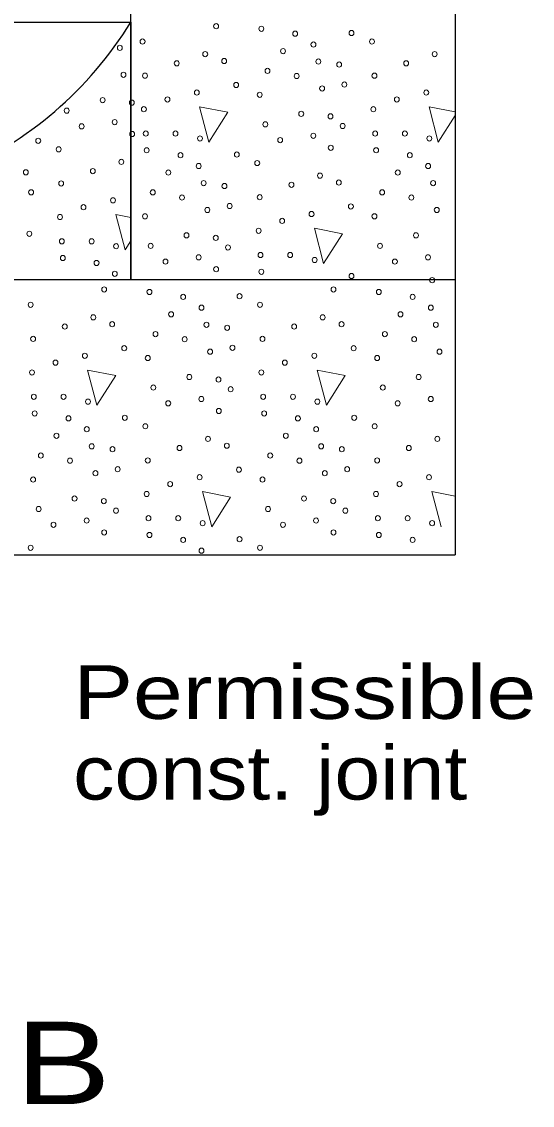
# Model space of a CAD drawing. Extents: x -410.5 to -376.5, y 1617.6 to 1661.6.
# Drawn here: x -391.413 to -389.927, y 1650.531 to 1653.682 of the extents above; entities that cross this region are included whole.
import ezdxf

# ---------------------------------------------------------------- set-up
doc = ezdxf.new("R2010")
doc.units = 0
doc.header["$LTSCALE"] = 0.062
doc.layers.add('1', color=7, linetype='Continuous', lineweight=13)

msp = doc.modelspace()

# ---------------------------------------------------------------- linework, layer by layer
at = {"layer": '1', "lineweight": 25}
for p, q in [((-393.83325, 1653.681), (-391.09567, 1653.681)), ((-390.15167, 1652.9315), (-391.09567, 1652.9315))]:
    msp.add_line(p, q, dxfattribs=at)
at = {"layer": '1'}
for p, q in [((-390.15158, 1653.41992), (-390.22783, 1653.43475)), ((-390.22783, 1653.43475), (-390.20083, 1653.33233)), ((-390.20083, 1653.33233), (-390.15158, 1653.40975)), ((-391.09567, 1653.11275), (-391.1395, 1653.12133)), ((-391.1395, 1653.12133), (-391.1125, 1653.01892)), ((-391.1125, 1653.01892), (-391.09567, 1653.04542)), ((-390.21983, 1652.31592), (-390.19292, 1652.21358)), ((-390.15175, 1652.30267), (-390.21983, 1652.31592))]:
    msp.add_line(p, q, dxfattribs=at)
at = {"layer": '1', "lineweight": 25}
for points in [[(-391.09567, 1656.03808), (-391.07275, 1656.04358), (-390.86258, 1655.99133), (-390.75258, 1656.01533), (-390.70333, 1656.02033), (-390.53658, 1656.01175), (-390.38608, 1655.98), (-390.15167, 1656.00792), (-390.15167, 1652.13192)], [(-391.09567, 1652.9315), (-391.09567, 1653.681), (-391.09567, 1656.03808)], [(-391.09567, 1653.681), (-391.09567, 1652.9315), (-393.18867, 1652.9315)], [(-390.15167, 1652.9315), (-394.16367, 1652.9315), (-394.16367, 1652.78158), (-393.83325, 1652.78158), (-393.83325, 1652.63167), (-394.27908, 1652.63167), (-394.54583, 1652.78158), (-394.77725, 1652.78158)], [(-394.77725, 1652.78158), (-394.77725, 1652.13192), (-390.15167, 1652.13192)]]:
    msp.add_lwpolyline(points, dxfattribs=at)
at = {"layer": '1'}
for points in [[(-390.89542, 1653.43475), (-390.86842, 1653.33233), (-390.81342, 1653.41875)], [(-390.56158, 1653.08142), (-390.53458, 1652.97892), (-390.47967, 1653.06542)], [(-391.22117, 1652.66925), (-391.19417, 1652.56683), (-391.13917, 1652.65333)], [(-390.55358, 1652.66925), (-390.52667, 1652.56683), (-390.47167, 1652.65333)], [(-390.88733, 1652.31592), (-390.86033, 1652.21358), (-390.8055, 1652.3)]]:
    msp.add_lwpolyline(points, close=True, dxfattribs=at)
at = {"layer": '1', "lineweight": 25}
msp.add_ellipse((-391.98484, 1654.29513), major_axis=(0, 1.12397), ratio=0.944543, start_param=3.5092821, end_param=4.1343748, dxfattribs=at)
at = {"layer": '1'}
for centre, major_axis in [((-390.8475, 1653.66907), (0, -0.00756)), ((-390.71567, 1653.66177), (0, -0.00756)), ((-390.4534, 1653.64934), (0, -0.00756)), ((-391.06144, 1653.62455), (0, -0.00756)), ((-390.61738, 1653.64746), (0, 0.00756)), ((-390.39393, 1653.62455), (0, -0.00756)), ((-391.12767, 1653.60631), (0, 0.00756)), ((-390.87904, 1653.58798), (0, -0.00756)), ((-390.65259, 1653.59687), (0, 0.00756)), ((-390.56426, 1653.61595), (0, 0.00756)), ((-390.21154, 1653.58798), (0, -0.00756)), ((-390.96198, 1653.5613), (0, -0.00756)), ((-390.82409, 1653.56796), (0, -0.00756)), ((-390.5498, 1653.56637), (0, 0.00756)), ((-390.48944, 1653.55771), (0, -0.00756)), ((-390.29447, 1653.5613), (0, -0.00756)), ((-391.11693, 1653.52804), (0, 0.00756)), ((-391.05421, 1653.52526), (0, -0.00756)), ((-390.69793, 1653.53933), (0, 0.00756)), ((-390.61293, 1653.52438), (0, 0.00756)), ((-390.3867, 1653.52526), (0, -0.00756)), ((-390.78899, 1653.49829), (0, 0.00756)), ((-390.47414, 1653.49958), (0, -0.00756)), ((-390.90341, 1653.47632), (0, -0.00756)), ((-390.72046, 1653.46967), (0, 0.00756)), ((-390.53906, 1653.4881), (0, 0.00756)), ((-390.2359, 1653.47632), (0, -0.00756)), ((-391.17756, 1653.45431), (0, 0.00756)), ((-391.09251, 1653.44695), (0, 0.00756)), ((-390.98907, 1653.4563), (0, -0.00756)), ((-390.32156, 1653.4563), (0, -0.00756)), ((-391.28208, 1653.42374), (0, 0.00756)), ((-391.05749, 1653.42768), (0, -0.00756)), ((-390.59969, 1653.41437), (0, 0.00756)), ((-390.51464, 1653.407), (0, 0.00756)), ((-390.38998, 1653.42768), (0, -0.00756)), ((-391.23881, 1653.37792), (0, 0.00756)), ((-391.14241, 1653.39035), (0, 0.00756)), ((-390.70421, 1653.3838), (0, 0.00756)), ((-390.47921, 1653.37903), (0, -0.00756)), ((-391.36502, 1653.33593), (0, -0.00756)), ((-391.09162, 1653.35566), (0, -0.00756)), ((-391.0521, 1653.35706), (0, -0.00756)), ((-390.96554, 1653.35706), (0, 0.00756)), ((-390.8944, 1653.34275), (0, -0.00756)), ((-390.66094, 1653.33798), (0, 0.00756)), ((-390.56454, 1653.35041), (0, 0.00756)), ((-390.38459, 1653.35706), (0, -0.00756)), ((-390.29803, 1653.35706), (0, 0.00756)), ((-390.22689, 1653.34275), (0, -0.00756)), ((-391.30556, 1653.31114), (0, -0.00756)), ((-391.04943, 1653.30842), (0, -0.00756)), ((-390.51375, 1653.31572), (0, -0.00756)), ((-390.38192, 1653.30842), (0, -0.00756)), ((-391.12316, 1653.27457), (0, -0.00756)), ((-390.95113, 1653.29411), (0, 0.00756)), ((-390.78715, 1653.29599), (0, -0.00756)), ((-390.72769, 1653.2712), (0, -0.00756)), ((-390.28363, 1653.29411), (0, 0.00756)), ((-391.40107, 1653.2443), (0, -0.00756)), ((-391.2061, 1653.24789), (0, -0.00756)), ((-390.98635, 1653.24352), (0, 0.00756)), ((-390.89801, 1653.2626), (0, 0.00756)), ((-390.31884, 1653.24352), (0, 0.00756)), ((-390.2305, 1653.2626), (0, 0.00756)), ((-391.29833, 1653.21185), (0, -0.00756)), ((-390.88355, 1653.21302), (0, 0.00756)), ((-390.62823, 1653.20795), (0, -0.00756)), ((-390.54529, 1653.23463), (0, -0.00756)), ((-390.49033, 1653.21461), (0, -0.00756)), ((-390.21604, 1653.21302), (0, 0.00756)), ((-391.38577, 1653.18617), (0, -0.00756)), ((-391.03168, 1653.18598), (0, 0.00756)), ((-390.8232, 1653.20436), (0, -0.00756)), ((-390.36417, 1653.18598), (0, 0.00756)), ((-391.14753, 1653.16291), (0, -0.00756)), ((-390.94668, 1653.17103), (0, 0.00756)), ((-390.8079, 1653.14623), (0, -0.00756)), ((-390.72046, 1653.17191), (0, -0.00756)), ((-390.45523, 1653.14494), (0, 0.00756)), ((-390.27918, 1653.17103), (0, 0.00756)), ((-391.30161, 1653.11427), (0, -0.00756)), ((-391.23319, 1653.14289), (0, -0.00756)), ((-391.05421, 1653.11632), (0, 0.00756)), ((-390.87281, 1653.13475), (0, 0.00756)), ((-390.56965, 1653.12297), (0, -0.00756)), ((-390.3867, 1653.11632), (0, 0.00756)), ((-390.20531, 1653.13475), (0, 0.00756)), ((-390.65532, 1653.10295), (0, -0.00756)), ((-391.39083, 1653.06562), (0, -0.00756)), ((-390.93345, 1653.06102), (0, 0.00756)), ((-390.84839, 1653.05365), (0, 0.00756)), ((-390.72374, 1653.07433), (0, -0.00756)), ((-390.26594, 1653.06102), (0, 0.00756)), ((-391.29621, 1653.04366), (0, -0.00756)), ((-391.20966, 1653.04366), (0, 0.00756)), ((-391.13851, 1653.02934), (0, -0.00756)), ((-391.03797, 1653.03045), (0, 0.00756)), ((-390.81296, 1653.02568), (0, -0.00756)), ((-390.37046, 1653.03045), (0, 0.00756)), ((-391.29354, 1652.99501), (0, -0.00756)), ((-390.89829, 1652.99706), (0, 0.00756)), ((-390.71834, 1653.00371), (0, -0.00756)), ((-390.63179, 1653.00371), (0, 0.00756)), ((-390.56064, 1652.9894), (0, -0.00756)), ((-390.23078, 1652.99706), (0, 0.00756)), ((-391.19525, 1652.9807), (0, 0.00756)), ((-390.99469, 1652.98463), (0, 0.00756)), ((-390.8475, 1652.96237), (0, -0.00756)), ((-390.71567, 1652.95507), (0, -0.00756)), ((-390.32718, 1652.98463), (0, 0.00756)), ((-391.14213, 1652.94919), (0, 0.00756)), ((-390.4534, 1652.94264), (0, -0.00756)), ((-390.21891, 1652.93063), (0, -0.00756)), ((-391.17328, 1652.9036), (0, -0.00756)), ((-391.04145, 1652.8963), (0, -0.00756)), ((-390.50577, 1652.9036), (0, -0.00756)), ((-390.37394, 1652.8963), (0, -0.00756)), ((-390.94316, 1652.88199), (0, 0.00756)), ((-390.77917, 1652.88387), (0, -0.00756)), ((-390.27565, 1652.88199), (0, 0.00756)), ((-391.38722, 1652.85908), (0, -0.00756)), ((-390.97837, 1652.8314), (0, 0.00756)), ((-390.89004, 1652.85048), (0, 0.00756)), ((-390.71971, 1652.85908), (0, -0.00756)), ((-390.31086, 1652.8314), (0, 0.00756)), ((-390.22253, 1652.85048), (0, 0.00756)), ((-391.20482, 1652.82251), (0, -0.00756)), ((-391.14986, 1652.80248), (0, -0.00756)), ((-390.87557, 1652.80089), (0, 0.00756)), ((-390.53731, 1652.82251), (0, -0.00756)), ((-390.48235, 1652.80248), (0, -0.00756)), ((-390.20806, 1652.80089), (0, 0.00756)), ((-391.28776, 1652.79583), (0, -0.00756)), ((-391.0237, 1652.77386), (0, 0.00756)), ((-390.81522, 1652.79224), (0, -0.00756)), ((-390.62025, 1652.79583), (0, -0.00756)), ((-390.3562, 1652.77386), (0, 0.00756)), ((-391.37999, 1652.75979), (0, -0.00756)), ((-390.93871, 1652.7589), (0, 0.00756)), ((-390.71248, 1652.75979), (0, -0.00756)), ((-390.2712, 1652.7589), (0, 0.00756)), ((-391.22919, 1652.71085), (0, -0.00756)), ((-391.11476, 1652.73281), (0, 0.00756)), ((-391.04623, 1652.70419), (0, 0.00756)), ((-390.86484, 1652.72263), (0, 0.00756)), ((-390.79992, 1652.73411), (0, -0.00756)), ((-390.56168, 1652.71085), (0, -0.00756)), ((-390.44725, 1652.73281), (0, 0.00756)), ((-390.37872, 1652.70419), (0, 0.00756)), ((-390.19733, 1652.72263), (0, 0.00756)), ((-391.31485, 1652.69082), (0, -0.00756)), ((-390.64734, 1652.69082), (0, -0.00756)), ((-391.38327, 1652.6622), (0, -0.00756)), ((-390.92547, 1652.64889), (0, 0.00756)), ((-390.84042, 1652.64153), (0, 0.00756)), ((-390.71576, 1652.6622), (0, -0.00756)), ((-390.25796, 1652.64889), (0, 0.00756)), ((-391.02999, 1652.61833), (0, 0.00756)), ((-390.80498, 1652.61356), (0, -0.00756)), ((-390.36248, 1652.61833), (0, 0.00756)), ((-391.37787, 1652.59159), (0, -0.00756)), ((-391.29132, 1652.59159), (0, 0.00756)), ((-391.22017, 1652.57728), (0, -0.00756)), ((-390.89031, 1652.58494), (0, 0.00756)), ((-390.71036, 1652.59159), (0, -0.00756)), ((-390.62381, 1652.59159), (0, 0.00756)), ((-390.55267, 1652.57728), (0, -0.00756)), ((-390.22281, 1652.58494), (0, 0.00756)), ((-390.98671, 1652.57251), (0, 0.00756)), ((-390.83953, 1652.55025), (0, -0.00756)), ((-390.3192, 1652.57251), (0, 0.00756)), ((-391.3752, 1652.54295), (0, -0.00756)), ((-391.27691, 1652.52864), (0, 0.00756)), ((-391.11293, 1652.53052), (0, -0.00756)), ((-390.70769, 1652.54295), (0, -0.00756)), ((-390.6094, 1652.52864), (0, 0.00756)), ((-390.44542, 1652.53052), (0, -0.00756)), ((-391.22379, 1652.49713), (0, 0.00756)), ((-391.05346, 1652.50573), (0, -0.00756)), ((-390.55628, 1652.49713), (0, 0.00756)), ((-390.38596, 1652.50573), (0, -0.00756)), ((-391.31212, 1652.47805), (0, 0.00756)), ((-390.87107, 1652.46916), (0, -0.00756)), ((-390.64461, 1652.47805), (0, 0.00756)), ((-390.20356, 1652.46916), (0, -0.00756)), ((-391.35746, 1652.42051), (0, 0.00756)), ((-391.20933, 1652.44754), (0, 0.00756)), ((-391.14897, 1652.43889), (0, -0.00756)), ((-390.95401, 1652.44248), (0, -0.00756)), ((-390.81611, 1652.44913), (0, -0.00756)), ((-390.68995, 1652.42051), (0, 0.00756)), ((-390.54182, 1652.44754), (0, 0.00756)), ((-390.48146, 1652.43889), (0, -0.00756)), ((-390.2865, 1652.44248), (0, -0.00756)), ((-391.27246, 1652.40555), (0, 0.00756)), ((-391.04623, 1652.40644), (0, -0.00756)), ((-390.60495, 1652.40555), (0, 0.00756)), ((-390.37872, 1652.40644), (0, -0.00756)), ((-391.19859, 1652.36928), (0, 0.00756)), ((-391.13368, 1652.38076), (0, -0.00756)), ((-390.89543, 1652.3575), (0, -0.00756)), ((-390.78101, 1652.37946), (0, 0.00756)), ((-390.53108, 1652.36928), (0, 0.00756)), ((-390.46617, 1652.38076), (0, -0.00756)), ((-390.22792, 1652.3575), (0, -0.00756)), ((-391.37999, 1652.35084), (0, 0.00756)), ((-390.98109, 1652.33747), (0, -0.00756)), ((-390.71248, 1652.35084), (0, 0.00756)), ((-390.31359, 1652.33747), (0, -0.00756)), ((-391.25922, 1652.29554), (0, 0.00756)), ((-391.04951, 1652.30885), (0, -0.00756)), ((-390.59171, 1652.29554), (0, 0.00756)), ((-390.38201, 1652.30885), (0, -0.00756)), ((-391.36374, 1652.26498), (0, 0.00756)), ((-391.17417, 1652.28818), (0, 0.00756)), ((-390.69624, 1652.26498), (0, 0.00756)), ((-390.50666, 1652.28818), (0, 0.00756)), ((-391.22407, 1652.23159), (0, 0.00756)), ((-391.13874, 1652.26021), (0, -0.00756)), ((-391.04412, 1652.23824), (0, -0.00756)), ((-390.95757, 1652.23824), (0, 0.00756)), ((-390.55656, 1652.23159), (0, 0.00756)), ((-390.47123, 1652.26021), (0, -0.00756)), ((-390.37661, 1652.23824), (0, -0.00756)), ((-390.29006, 1652.23824), (0, 0.00756)), ((-391.32047, 1652.21916), (0, 0.00756)), ((-390.88642, 1652.22393), (0, -0.00756)), ((-390.65296, 1652.21916), (0, 0.00756)), ((-390.21891, 1652.22393), (0, -0.00756)), ((-391.17328, 1652.1969), (0, -0.00756)), ((-391.04145, 1652.1896), (0, -0.00756)), ((-390.94316, 1652.17529), (0, 0.00756)), ((-390.77917, 1652.17717), (0, -0.00756)), ((-390.50577, 1652.1969), (0, -0.00756)), ((-390.37394, 1652.1896), (0, -0.00756)), ((-390.27565, 1652.17529), (0, 0.00756)), ((-391.38722, 1652.15238), (0, -0.00756)), ((-390.89004, 1652.14378), (0, 0.00756)), ((-390.71971, 1652.15238), (0, -0.00756))]:
    msp.add_ellipse(centre, major_axis=major_axis, ratio=0.944543, dxfattribs=at)

# ---------------------------------------------------------------- texts
for s, height, width, p in [('Permissible', 0.156, 1.25, (-391.26325, 1651.65467)), ('const. joint', 0.156, 1.15, (-391.26325, 1651.42)), ('SECTION B-B', 0.24, 1.3, (-393.81975, 1650.53425))]:
    msp.add_text(s, height=height, dxfattribs=dict(at, width=width)).set_placement(p)

doc.saveas('drawing.dxf')
